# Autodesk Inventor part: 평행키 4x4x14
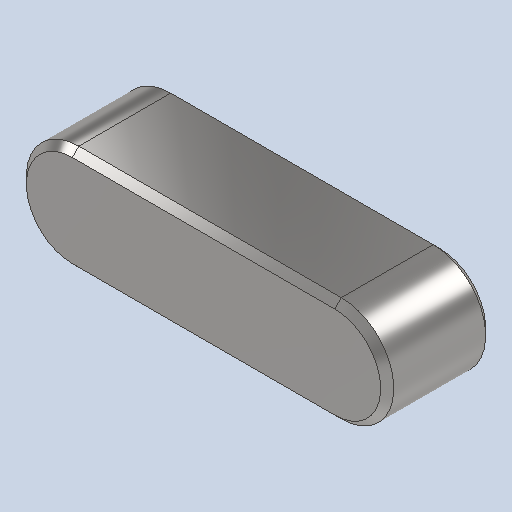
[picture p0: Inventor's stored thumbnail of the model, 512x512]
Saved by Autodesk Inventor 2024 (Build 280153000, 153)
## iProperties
Created: 2024-08
Part Number: 평행키 4x4x14
Material: 강철, 연강
Description: 키 및 해당 키홈
Document SubType Name: Modeling
Designer: user
Density: 7.85 g/cm^3
Appearance: 기본값
Author: jhkim
Sending System: Autodesk Inventor 2025
Preprocessor: ST-DEVELOPER v20
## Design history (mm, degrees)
feature "Solid1"
node "솔리드1"
